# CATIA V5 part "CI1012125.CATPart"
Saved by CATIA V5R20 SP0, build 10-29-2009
Part number: CI1012125
Bounding box of the stored display mesh (mm): x -12 to 12, y -10.269 to 93, z -13.002 to 14.106
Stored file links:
  C:\Users\Raffaele\Desktop\3D X SITO CF\BOLEX\19-INCLINED ASSEMBLY REF_CI\CI1012125.CATPart
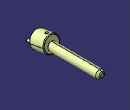
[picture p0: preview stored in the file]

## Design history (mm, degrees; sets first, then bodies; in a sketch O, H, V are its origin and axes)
Set1
  DatumSurface1 to DatumSurface16 "MANIFOLD_SOLID_BREP #379"
  DatumSurface17 to DatumSurface39 "MANIFOLD_SOLID_BREP #1096"
Body1 (main body)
